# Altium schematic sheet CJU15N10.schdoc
size 127 x 101 mm
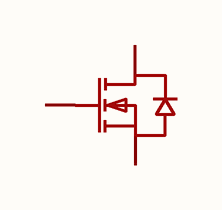
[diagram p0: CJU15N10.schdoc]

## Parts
Q?  cju15n10  [TO-252-2_L6.6-W6.1-P4.57-LS9.9-BR-CW]  (value not drawn)

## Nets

Not connected (* = marked no-connect by the designer): Q? 1(G) 2(D) 3(S)

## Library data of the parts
Q? = cju15n10: 数量:1个N沟道;漏源电压(Vdss):100V;连续漏极电流(Id):15A;导通电阻(RDS(on)):100mΩ@10V;耗散功率(Pd):45W;阈值电压(Vgs(th)):3V;; Manufacturer: CJ(江苏长电/长晶); AddInBom: yes; ModelId: ce57f84d66384067af8a68020b6de06d; ModelName: TO-252-2L-3P_L6.6-W6.1-H2.3-LS10.1-P4.6; ModelTransform: 259.842,390.52442,0,90,0,0,-39.39,0,0; Number: 1个N沟道; Drain to Source Voltage: 100V; Current - Continuous Drain(Id): 15A; Pd - Power Dissipation: 45W; Gate Threshold Voltage (Vgs(th)): 3V; Gate Charge(Qg): 36nC@10V; Input Capacitance(Ciss): 1.5nF; Reverse Transfer Capacitance (Crss@Vds): 90pF; Type: N沟道; Output Capacitance(Coss): 92pF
